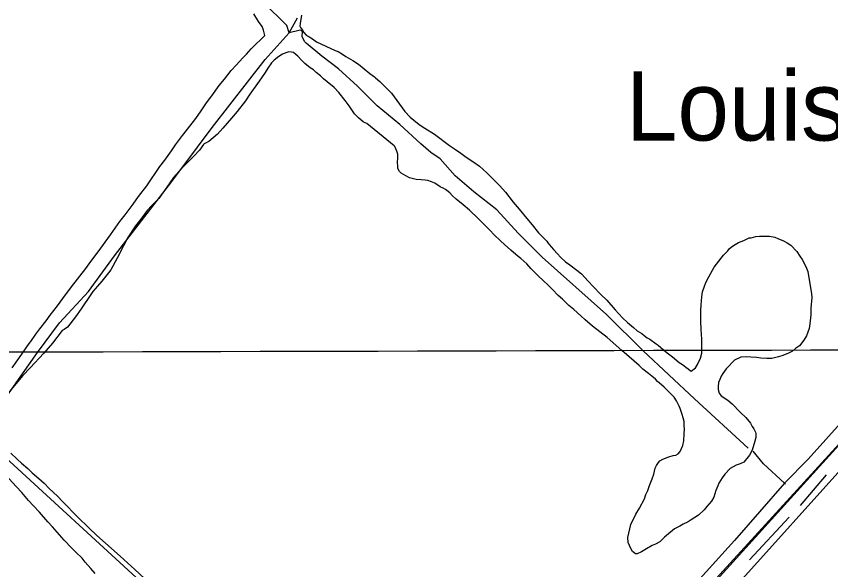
# Model space of a CAD drawing. Extents: x 3355677 to 3393573, y 612928 to 638357.
# Drawn here: x 3381245 to 3382949, y 623971 to 625128 of the extents above; entities that cross this region are included whole.
import ezdxf

# ---------------------------------------------------------------- set-up
doc = ezdxf.new("R2010")
doc.units = 0
for name, color, linetype in [('V-GRID-MAJR', 7, 'Continuous'), ('V-ROAD-CNTR', 7, 'Continuous'), ('V-SITE-OTLN', 7, 'Continuous'), ('V-SITE-VEGE', 7, 'Continuous'), ('V-TOPO-GNAM-IDEN', 7, 'Continuous'), ('V-TOPO-SHOR', 7, 'Continuous')]:
    doc.layers.add(name, color=color, linetype=linetype)

msp = doc.modelspace()

# ---------------------------------------------------------------- linework, layer by layer
at = {"layer": 'V-GRID-MAJR'}
msp.add_spline([(3359794.3370000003, 624373.309), (3365058.395, 624385.176), (3370322.451, 624397.809), (3375586.505, 624411.208), (3380850.557, 624425.373), (3386114.607, 624440.303), (3391378.654, 624455.998), (3391378.6550000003, 624455.998)], degree=3, dxfattribs=at)
at = {"layer": 'V-ROAD-CNTR'}
for points in [[(3379694.12, 620644.703), (3382535.952, 623757.551), (3384147.191, 625535.174)], [(3380013.162, 620986.814), (3380148.012, 621136.819), (3380307.222, 621312.087), (3380410.13, 621425.376), (3380539.8310000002, 621568.355), (3380711.0500000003, 621757.099), (3380717.8310000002, 621764.574), (3381051.174, 622131.482), (3381182.666, 622275.468), (3381362.681, 622472.594), (3381699.823, 622844.278), (3382051.221, 623227.438), (3382358.918, 623567.588), (3382672.3200000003, 623912.5210000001), (3382981.928, 624250.768), (3383331.417, 624635.829), (3383600.1890000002, 624929.17), (3383887.949, 625245.439), (3384037.357, 625413.979), (3384075.974, 625457.542)]]:
    msp.add_lwpolyline(points, dxfattribs=at)
at = {"layer": 'V-SITE-OTLN'}
msp.add_line((3382628.295874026, 623801.3719021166), (3383081.9987352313, 624305.195794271), dxfattribs=at)
at = {"layer": 'V-SITE-VEGE'}
for points in [[(3381754.508, 625077.6630000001), (3381762.285, 625085.484), (3381764.503, 625088.273), (3381762.242, 625099.41), (3381758.879, 625106.642), (3381751.606, 625117.199), (3381741.5300000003, 625133.323)], [(3381841.8000000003, 625130.286), (3381838.509, 625113.009), (3381837.971, 625107.437), (3381839.65, 625104.657), (3381843.566, 625099.099), (3381846.365, 625094.094), (3381851.395, 625088.54), (3381855.301, 625086.324), (3381864.23, 625080.78), (3381873.159, 625074.681), (3381912.2060000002, 625056.417), (3381918.338, 625054.207), (3381927.267, 625048.665), (3381933.966, 625044.229), (3381949.032, 625035.361), (3381960.75, 625028.159)], [(3381235.7830000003, 624393.209), (3381251.315, 624414.4180000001), (3381271.8340000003, 624444.003), (3381275.164, 624448.47), (3381285.701, 624463.541), (3381294.022, 624474.707), (3381307.34, 624491.458), (3381315.659, 624503.178), (3381331.193, 624522.72), (3381342.289, 624538.351), (3381360.596, 624562.357), (3381390.558, 624600.88), (3381400.54, 624615.394), (3381416.074, 624635.493), (3381442.145, 624671.221), (3381446.5810000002, 624678.475), (3381461.556, 624699.129), (3381472.654, 624713.086), (3381489.299, 624735.417), (3381500.3910000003, 624751.0480000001), (3381517.588, 624773.938), (3381544.7600000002, 624814.122), (3381555.302, 624827.522), (3381569.169, 624847.06), (3381578.042, 624859.344), (3381592.467, 624878.88), (3381603.0100000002, 624892.28), (3381620.2090000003, 624914.611), (3381631.301, 624930.242), (3381642.948, 624946.984), (3381654.044, 624961.502), (3381669.574, 624983.273), (3381680.674, 624996.675), (3381694.543, 625014.539), (3381705.092, 625025.713), (3381718.412, 625041.35), (3381726.1890000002, 625049.171), (3381736.181, 625060.341), (3381747.842, 625072.074), (3381754.508, 625077.6630000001)], [(3382641.565, 624240.385), (3382642.075, 624255.985), (3382643.16, 624264.898), (3382642.024, 624272.694), (3382641.9990000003, 624281.0480000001), (3382640.303, 624288.843), (3382638.055, 624295.519), (3382633.561, 624307.76), (3382631.876, 624312.768), (3382626.27, 624324.447), (3382621.236, 624331.6730000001), (3382600.007, 624352.775), (3382594.4220000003, 624357.213), (3382586.603, 624364.432), (3382582.132, 624369.432), (3382574.315, 624375.533), (3382567.616, 624381.085), (3382555.889, 624390.518), (3382548.0670000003, 624397.735), (3382527.403, 624416.054), (3382511.767, 624429.375), (3382481.051, 624456.574), (3382450.341, 624480.433), (3382435.2660000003, 624493.198), (3382425.769, 624502.083), (3382411.247, 624515.407), (3382401.1950000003, 624523.73), (3382387.789, 624536.501), (3382378.8540000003, 624544.2710000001), (3382366.559, 624557.047), (3382357.063, 624566.486), (3382347.5700000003, 624574.813), (3382336.951, 624585.365), (3382321.872, 624599.801), (3382312.926, 624610.356), (3382300.6380000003, 624621.458), (3382295.053, 624625.899), (3382279.419, 624639.219), (3382266.574, 624650.878), (3382258.194, 624658.652), (3382244.787, 624671.419), (3382235.291, 624680.861), (3382220.762, 624695.856), (3382211.2660000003, 624705.295), (3382192.832, 624722.507), (3382179.427, 624734.164), (3382165.468, 624745.819), (3382157.647, 624753.036), (3382152.058, 624759.148), (3382145.916, 624764.1410000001), (3382142.5700000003, 624765.802), (3382138.107, 624768.572), (3382131.969, 624771.8960000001), (3382120.808, 624779.103), (3382113.558, 624781.866), (3382105.751, 624784.629), (3382100.176, 624785.167), (3382091.8200000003, 624786.257), (3382081.236, 624786.781), (3382067.299, 624790.64), (3382059.49, 624794.514), (3382050.004, 624800.056), (3382046.6520000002, 624803.388), (3382043.291, 624810.061), (3382042.723, 624813.4010000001), (3382042.6890000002, 624824.54), (3382043.2290000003, 624830.113), (3382043.201, 624839.583), (3382040.952, 624846.259), (3382036.469, 624855.715), (3382035.349, 624857.384), (3381978.394, 624903.9990000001), (3381971.142, 624906.761), (3381961.09, 624915.6460000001), (3381952.7120000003, 624923.973), (3381940.9620000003, 624940.647), (3381932.574, 624952.319), (3381919.71, 624968.99), (3381909.6550000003, 624978.986), (3381895.136, 624991.196), (3381887.319, 624997.299), (3381881.173, 625003.408), (3381872.24, 625010.622), (3381866.651, 625016.176), (3381859.9560000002, 625020.6140000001), (3381848.788, 625029.49), (3381842.085, 625035.5970000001), (3381833.705, 625044.483), (3381829.793, 625048.37), (3381824.769, 625052.253), (3381820.8680000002, 625052.7980000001), (3381815.295, 625053.8960000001), (3381810.843, 625052.767), (3381801.94, 625048.841), (3381794.16, 625044.362), (3381784.1550000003, 625036.535), (3381778.6010000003, 625030.948), (3381770.8370000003, 625019.784), (3381765.295, 625010.855), (3381758.086, 624999.693), (3381749.769, 624987.414)], [(3381960.75, 625028.159), (3381984.761, 625008.733), (3381994.251, 625001.522), (3381996.486, 624999.3), (3382005.421, 624991.53), (3382013.24, 624984.313), (3382030.001, 624967.652), (3382040.632, 624952.09), (3382057.412, 624929.304), (3382068.588, 624917.083), (3382087.573, 624902.1), (3382099.291, 624894.338), (3382119.9390000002, 624881.587), (3382151.204, 624857.734), (3382163.484, 624849.415), (3382175.204, 624841.653), (3382186.3680000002, 624833.887), (3382201.994, 624823.352), (3382213.717, 624815.033), (3382229.358, 624800.595), (3382239.97, 624790.605), (3382256.176, 624773.385), (3382268.47, 624760.055), (3382284.686, 624739.493), (3382296.983, 624725.05), (3382313.197, 624705.0480000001), (3382323.8200000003, 624692.268), (3382337.238, 624675.042), (3382354.558, 624657.827), (3382356.7970000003, 624654.493), (3382364.063, 624646.159), (3382368.536, 624640.603), (3382377.475, 624631.162), (3382383.623, 624624.496), (3382393.679, 624614.4990000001), (3382403.167, 624608.4), (3382417.684, 624597.304), (3382427.174, 624589.536), (3382441.148, 624574.539), (3382451.7600000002, 624563.43), (3382467.968, 624546.213), (3382480.256, 624534.554), (3382497.5840000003, 624514.553), (3382513.233, 624497.333), (3382523.287, 624487.894), (3382536.13, 624477.351), (3382543.949, 624470.693), (3382553.435, 624464.5920000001), (3382558.461, 624460.709), (3382564.6010000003, 624455.714), (3382570.182, 624452.947), (3382583.578, 624443.518), (3382587.487, 624440.188), (3382599.2120000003, 624430.753), (3382606.472, 624424.65), (3382617.6380000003, 624415.77), (3382631.599, 624404.1140000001), (3382638.8510000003, 624400.238), (3382645.552, 624394.688), (3382650.578, 624390.805), (3382654.488, 624387.474), (3382656.72, 624386.367), (3382665.61, 624393.078), (3382670.046, 624399.775), (3382676.688, 624413.165), (3382679.441, 624423.755), (3382679.359, 624451.608), (3382678.7630000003, 624464.414), (3382677.6240000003, 624472.7660000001), (3382677.0100000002, 624491.144), (3382676.944, 624512.867), (3382677.464, 624525.125), (3382679.086, 624541.281), (3382680.727, 624551.87), (3382684.589, 624563.578), (3382686.799, 624569.712), (3382690.119, 624576.964), (3382705.077, 624603.745), (3382724.497, 624628.868), (3382733.381, 624637.808), (3382737.2660000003, 624642.274), (3382743.379, 624647.306), (3382748.935, 624651.2220000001), (3382756.167, 624655.144), (3382767.292, 624659.633), (3382777.859, 624664.677), (3382782.3140000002, 624665.2490000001), (3382792.332, 624667.506), (3382800.127, 624668.644), (3382820.736, 624668.708), (3382831.883, 624666.512), (3382838.019, 624663.746), (3382849.732, 624658.7710000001), (3382857.543, 624654.335), (3382865.356, 624649.348), (3382878.205, 624636.5750000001), (3382884.363, 624626.566), (3382889.397, 624619.341), (3382896.682, 624604.882), (3382901.169, 624594.8690000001), (3382908.554, 624547.546)], [(3381749.769, 624987.414), (3381733.127, 624965.084), (3381724.255, 624951.688), (3381707.058, 624928.8), (3381694.846, 624914.841), (3381677.082, 624894.172), (3381665.427, 624881.327), (3381647.648, 624866.235), (3381638.194, 624861.193), (3381636.525, 624860.0750000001), (3381628.208, 624848.352), (3381615.992, 624835.505), (3381597.668, 624816.51), (3381585.45, 624804.22), (3381573.795, 624790.818), (3381564.364, 624777.977), (3381551.611, 624759), (3381542.735, 624747.275), (3381528.2970000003, 624732.194), (3381518.859, 624722.14), (3381504.99, 624703.716), (3381493.892, 624689.757), (3381478.3680000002, 624665.759), (3381468.954, 624647.906), (3381455.662, 624622.245), (3381442.367, 624598.253), (3381437.376, 624591.556), (3381424.06, 624574.246), (3381414.62, 624564.192), (3381405.185, 624553.023), (3381393.538, 624536.278), (3381387.4390000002, 624526.79), (3381380.23, 624516.185), (3381368.585, 624499.441), (3381351.9390000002, 624478.223), (3381344.714, 624473.189), (3381340.821, 624470.949), (3381320.849, 624444.71), (3381302.529, 624424.046), (3381273.6580000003, 624393.322), (3381258.667, 624377.1240000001), (3381230.364, 624343.6190000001)], [(3382908.554, 624547.546), (3382909.132, 624540.306), (3382907.528, 624518.022), (3382907.012, 624504.096), (3382905.4, 624485.152), (3382903.7600000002, 624475.121), (3382898.237, 624460.066), (3382892.693, 624451.137), (3382883.257, 624439.412), (3382875.4790000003, 624433.26), (3382868.811, 624427.671), (3382860.467, 624423.747), (3382848.788, 624418.696), (3382839.326, 624415.884), (3382825.412, 624412.4990000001), (3382814.826, 624412.468), (3382802.572, 624412.986), (3382793.653, 624414.631), (3382781.4, 624415.708), (3382773.042, 624416.241), (3382760.789, 624415.647), (3382747.4420000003, 624408.921), (3382741.8880000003, 624403.334), (3382736.336, 624397.1900000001), (3382730.2290000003, 624391.044), (3382723.0160000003, 624381.556), (3382719.6920000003, 624375.975), (3382716.9250000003, 624368.725), (3382714.162, 624362.589), (3382713.075, 624353.674), (3382713.091, 624348.104), (3382715.344, 624340.313), (3382719.8170000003, 624334.757), (3382733.213, 624325.328), (3382742.705, 624317.56), (3382748.292, 624312.006), (3382753.879, 624305.897), (3382760.025, 624299.787), (3382771.197, 624289.238), (3382780.702, 624277.571), (3382784.6240000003, 624270.339), (3382787.98, 624265.338), (3382791.341, 624258.6630000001), (3382791.9080000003, 624255.88), (3382791.933, 624247.524), (3382790.286, 624239.7220000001), (3382784.216, 624220.763), (3382778.678, 624210.167), (3382767.023, 624196.206), (3382759.237, 624192.284), (3382750.893, 624189.474), (3382738.656, 624182.752), (3382727.552, 624171.0210000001), (3382722.006, 624163.206), (3382714.799, 624152.045), (3382712.5870000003, 624146.468), (3382708.162, 624136.429), (3382704.305, 624122.492), (3382699.316, 624114.122), (3382689.877, 624103.509), (3382683.774, 624096.251), (3382672.113, 624085.0750000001), (3382657.103, 624075.001), (3382650.431, 624071.083), (3382640.42, 624066.041), (3382633.188, 624062.121), (3382622.066, 624056.5160000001), (3382600.955, 624039.185), (3382590.9590000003, 624029.13), (3382582.062, 624024.09), (3382575.386, 624021.284), (3382563.153, 624014.562), (3382552.5870000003, 624008.404), (3382543.6890000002, 624004.478), (3382540.346, 624004.468), (3382534.207, 624008.906), (3382530.287, 624015.576), (3382524.679, 624027.8150000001), (3382524.647, 624038.397), (3382528.4930000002, 624056.233), (3382530.6920000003, 624065.709), (3382541.211, 624086.908), (3382548.414, 624099.741), (3382558.938, 624119.2660000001), (3382562.252, 624128.1900000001), (3382566.127, 624136.556), (3382569.9930000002, 624147.15), (3382575.521, 624161.093), (3382578.835, 624170.571), (3382581.5810000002, 624183.3910000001), (3382584.348, 624188.968), (3382588.2290000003, 624195.108), (3382591.004, 624198.46), (3382597.676, 624202.376), (3382609.915, 624206.868), (3382619.377, 624209.684), (3382624.943, 624210.814), (3382629.949, 624213.616), (3382633.8340000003, 624218.082), (3382639.365, 624230.911), (3382641.565, 624240.385)], [(3381232.9790000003, 624214.957), (3381246.387, 624202.186), (3381255.325, 624193.861), (3381268.725, 624182.761), (3381278.221, 624173.876), (3381292.183, 624161.664), (3381302.795, 624152.229), (3381313.412, 624141.121), (3381330.728, 624124.462), (3381341.904, 624112.799), (3381373.7460000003, 624081.147)], [(3381409.754, 623963.172), (3381400.811, 623973.727), (3381389.074, 623987.06), (3381382.923, 623994.838), (3381369.515, 624007.609), (3381360.019, 624017.051), (3381344.933, 624032.599), (3381335.43, 624044.269), (3381320.341, 624060.933), (3381310.84, 624070.929), (3381293.5100000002, 624091.487), (3381280.099, 624105.371), (3381270.597, 624115.926), (3381256.066, 624132.593), (3381244.89, 624144.254), (3381229.244, 624161.476)], [(3381373.7460000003, 624081.147), (3381396.6550000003, 624058.379), (3381413.414, 624042.2760000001), (3381431.287, 624026.177), (3381462.003, 623999.534), (3381492.725, 623971.221), (3381512.83, 623952.3420000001), (3381531.819, 623936.2490000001), (3381577.614, 623896.28), (3381595.489, 623879.626), (3381625.085, 623855.207), (3381644.0700000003, 623838.553), (3381673.109, 623814.692), (3381692.6550000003, 623798.04), (3381711.65, 623779.159), (3381730.078, 623763.6190000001), (3381777.546, 623722.544)]]:
    msp.add_lwpolyline(points, dxfattribs=at)
at = {"layer": 'V-TOPO-SHOR'}
for p, q in [((3381167.927492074, 624254.681401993), (3382065.0307668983, 623434.2536207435)), ((3382885.256, 624105.5750000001), (3382939.862, 624169.041)), ((3382778.838, 623991.877), (3382861.71, 624080.938))]:
    msp.add_line(p, q, dxfattribs=at)
for points in [[(3381815.404, 625093.557), (3381810.607, 625108.7390000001), (3381795.366, 625123.89), (3381758.215, 625159.87), (3381702.96, 625214.791), (3381636.292, 625275.377), (3381461.0300000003, 625440.11), (3381281.029, 625601.979)], [(3381182.9790000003, 624274.394), (3381239.4220000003, 624354.872), (3381289.285, 624424.939), (3381335.3910000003, 624487.435), (3381395.66, 624552.807), (3381450.233, 624627.613), (3381563.166, 624773.453), (3381593.2800000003, 624813.225), (3381654.441, 624895.608), (3381765.498, 625037.6630000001), (3381815.404, 625093.557), (3381833.2600000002, 625124.789)], [(3381847.565, 625075.375), (3381842.785, 625085.808), (3381843.707, 625095.308), (3381839.896, 625099.0970000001), (3381836.1010000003, 625098.135), (3381815.404, 625093.557)], [(3382776.188, 624225.269), (3382663.8000000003, 624328.455), (3382556.169, 624428.809), (3382479.957, 624504.563), (3382344.722, 624624.7760000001), (3382295.18, 624674.9670000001), (3382250.395, 624723.2710000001), (3382201.841, 624761.116), (3382162.8000000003, 624794.24), (3382131.347, 624830.238), (3382112.31, 624843.476), (3382091.361, 624861.46), (3382047.546, 624902.1680000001), (3381999.941, 624940.965), (3381958.975, 624981.681), (3381918.971, 625018.603), (3381883.75, 625045.091), (3381851.377, 625071.586), (3381847.565, 625075.375)], [(3382851.991, 624151.707), (3382901.913, 624201.932), (3383006.432, 624318.459), (3383160.878, 624484.265), (3383311.5500000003, 624648.171), (3383507.4020000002, 624867.956), (3383548.843, 624910.5970000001)], [(3382853.944, 624149.886), (3382851.991, 624151.707), (3382808.467, 624192.263), (3382786.6550000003, 624218.652)], [(3382851.991, 624151.707), (3382747.4790000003, 624032.345), (3382556.325, 623821.08), (3382389.659, 623635.394), (3382162.722, 623384.337)]]:
    msp.add_lwpolyline(points, dxfattribs=at)

# ---------------------------------------------------------------- texts
at = {"layer": 'V-TOPO-GNAM-IDEN'}
msp.add_text('Louisville', height=144.999711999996, dxfattribs=at).set_placement((3382520.2679218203, 624868.3512366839))

doc.saveas('drawing.dxf')
